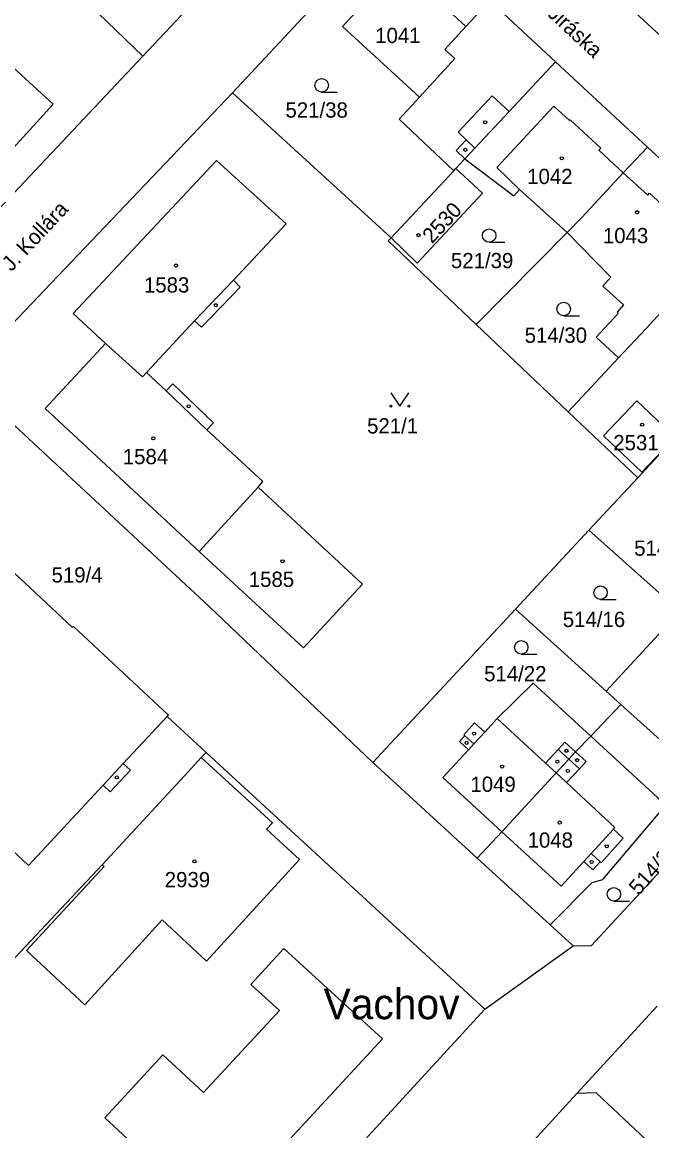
# Model space of a CAD drawing. Extents: x -679220 to -673243, y -1075091 to -1066557.
# Drawn here: x -675907.3 to -675837.1, y -1071866.6 to -1071743.1 of the extents above; entities that cross this region are included whole.
import ezdxf

# ---------------------------------------------------------------- set-up
doc = ezdxf.new("R2010")
doc.units = 0
for name, color, linetype in [('Hranice parcel', 7, 'Continuous'), ('Parcelní čísla', 7, 'Continuous'), ('Pop  PČ popisy', 7, 'Continuous'), ('Vnitřní kresba', 7, 'Continuous'), ('Značky budov', 7, 'Continuous'), ('Značky kultur', 7, 'Continuous')]:
    doc.layers.add(name, color=color, linetype=linetype)

msp = doc.modelspace()

# ---------------------------------------------------------------- linework, layer by layer
at = {"layer": 'Hranice parcel'}
for p, q in [((-675866.48, -1071732.32), (-675883.86, -1071750.99)), ((-675893.86, -1071746.89), (-675880.99, -1071733.17)), ((-675842.49, -1071738.77), (-675830.43, -1071749.89)), ((-675847.84, -1071747.53), (-675855.18, -1071740.72)), ((-675898.85, -1071742.09), (-675893.86, -1071746.89)), ((-675921.25, -1071775.94), (-675893.86, -1071746.89)), ((-675837.59, -1071757.04), (-675847.84, -1071747.53)), ((-675883.86, -1071750.99), (-675914.03, -1071782.61)), ((-675866.19, -1071767.13), (-675883.86, -1071750.99)), ((-675827.58, -1071766.32), (-675837.59, -1071757.04)), ((-675858.95, -1071759.4), (-675857.95, -1071758.34)), ((-675859.18, -1071759.65), (-675866.19, -1071767.13)), ((-675859.18, -1071759.65), (-675858.95, -1071759.4)), ((-675846.56, -1071766.55), (-675856.71, -1071776.78)), ((-675846.56, -1071766.55), (-675841.68, -1071771.5)), ((-675856.71, -1071776.78), (-675846.44, -1071786.53)), ((-675843.31, -1071778.2), (-675840.81, -1071780.5)), ((-675846.44, -1071786.53), (-675840.81, -1071780.5)), ((-675846.44, -1071786.53), (-675838.69, -1071793.89)), ((-675835.95, -1071790.96), (-675838.69, -1071793.89)), ((-675887.58, -1071802.09), (-675881, -1071794.9)), ((-675838.69, -1071793.89), (-675844.12, -1071799.72)), ((-675844.12, -1071799.72), (-675852.3, -1071808.5)), ((-675844.12, -1071799.72), (-675834.93, -1071807.9)), ((-675852.3, -1071808.5), (-675868.22, -1071825.58)), ((-675852.3, -1071808.5), (-675842.22, -1071817.63)), ((-675842.22, -1071817.63), (-675840.56, -1071819.13)), ((-675843.93, -1071822.65), (-675840.56, -1071819.13)), ((-675840.56, -1071819.13), (-675828.84, -1071829.74)), ((-675891.16, -1071820.48), (-675886.79, -1071824.5)), ((-675886.79, -1071824.5), (-675887.37, -1071825.05)), ((-675855.72, -1071853.08), (-675886.79, -1071824.5)), ((-675868.22, -1071825.58), (-675856.58, -1071836.24)), ((-675853.82, -1071833.33), (-675856.58, -1071836.24)), ((-675856.58, -1071836.24), (-675848.43, -1071843.7)), ((-675848.43, -1071843.7), (-675845.89, -1071846.03)), ((-675855.72, -1071853.08), (-675845.89, -1071846.03)), ((-675845.47, -1071862.48), (-675836.53, -1071852.75)), ((-675901.1, -1071902.37), (-675855.72, -1071853.08)), ((-675845.47, -1071862.48), (-675857.63, -1071875.7))]:
    msp.add_line(p, q, dxfattribs=at)
for points in [[(-675855.18, -1071740.72), (-675857.84, -1071743.59), (-675865.26, -1071736.73), (-675871.59, -1071743.6), (-675863.02, -1071751.44), (-675865.29, -1071753.91), (-675859.18, -1071759.65)], [(-675918.94, -1071760.27), (-675914.71, -1071764.13), (-675903.88, -1071752.24), (-675911.09, -1071745.65), (-675921.6, -1071757.18)], [(-675857.95, -1071758.34), (-675856.83, -1071757.13), (-675853.02, -1071753.07), (-675847.84, -1071747.53)], [(-675891.16, -1071820.48), (-675891.02, -1071820.34), (-675901.61, -1071810.45), (-675901.71, -1071810.56), (-675918.81, -1071794.59), (-675918.18, -1071793.92), (-675931.58, -1071781.37), (-675932.2, -1071782.05), (-675949.36, -1071766.12), (-675949.26, -1071766.01), (-675959.87, -1071756.16)], [(-675846.56, -1071766.55), (-675844.9, -1071764.88), (-675840.29, -1071759.88), (-675837.59, -1071757.04)], [(-675893.45, -1071782.14), (-675888.1, -1071776.37), (-675887.31, -1071777.1), (-675883.01, -1071772.64), (-675883.76, -1071771.84), (-675877.9, -1071765.58), (-675885.65, -1071758.5), (-675901.64, -1071775.55), (-675898.01, -1071778.89)], [(-675857.95, -1071758.34), (-675852.5, -1071762.45), (-675851.85, -1071761.73), (-675846.56, -1071766.55)], [(-675866.19, -1071767.13), (-675863.29, -1071769.94), (-675856.01, -1071762.17), (-675858.95, -1071759.4)], [(-675840.81, -1071780.5), (-675837.74, -1071777.22), (-675834.42, -1071773.65), (-675827.58, -1071766.32)], [(-675856.71, -1071776.78), (-675866.51, -1071767.47), (-675866.19, -1071767.13)], [(-675841.68, -1071771.5), (-675842.59, -1071772.51), (-675840.26, -1071774.6), (-675840.99, -1071775.43), (-675840.87, -1071775.55), (-675843.31, -1071778.2)], [(-675898.01, -1071778.89), (-675904.75, -1071786.16), (-675887.58, -1071802.09)], [(-675898.01, -1071778.89), (-675893.92, -1071782.64), (-675893.45, -1071782.14)], [(-675881, -1071794.9), (-675880.5, -1071794.3), (-675886.72, -1071788.53), (-675885.97, -1071787.73), (-675890.53, -1071783.41), (-675891.27, -1071784.2), (-675893.45, -1071782.14)], [(-675868.22, -1071825.58), (-675886.48, -1071808.2), (-675914.03, -1071782.61)], [(-675838.23, -1071793.24), (-675834.52, -1071789.33), (-675838.77, -1071785.29), (-675842.49, -1071789.2), (-675838.23, -1071793.24)], [(-675887.58, -1071802.09), (-675875.94, -1071812.81), (-675869.37, -1071805.71), (-675881, -1071794.9)], [(-675834.93, -1071807.9), (-675835.49, -1071810.37), (-675842.22, -1071817.63)], [(-675843.93, -1071822.65), (-675850.33, -1071816.76), (-675854.35, -1071820.68), (-675855.75, -1071822.21), (-675856.89, -1071821.16), (-675858.06, -1071822.51), (-675857.95, -1071822.61), (-675858.56, -1071823.27), (-675857.56, -1071824.19), (-675860.41, -1071827.28), (-675853.82, -1071833.33)], [(-675917.51, -1071826.9), (-675906.62, -1071837.07), (-675898.28, -1071828.12), (-675897.5, -1071828.86), (-675895.25, -1071826.46), (-675896.04, -1071825.71), (-675891.16, -1071820.48)], [(-675843.93, -1071822.65), (-675845.62, -1071824.41), (-675846.37, -1071825.22), (-675847.79, -1071826.76), (-675853.82, -1071833.33)], [(-675848.43, -1071843.7), (-675843.75, -1071838.95), (-675842.57, -1071838.65), (-675835.54, -1071830.36), (-675843.93, -1071822.65)], [(-675898.39, -1071836.99), (-675898.17, -1071837.19), (-675906.82, -1071846.56), (-675900.34, -1071852.59), (-675891.72, -1071843.14), (-675886.75, -1071847.74), (-675876.4, -1071836.42), (-675880.09, -1071833.04), (-675879.42, -1071832.31), (-675887.37, -1071825.05)], [(-675887.37, -1071825.05), (-675889.26, -1071827.11), (-675898.39, -1071836.99)], [(-675845.89, -1071846.03), (-675843.82, -1071845.98), (-675828.84, -1071829.74)], [(-675898.39, -1071836.99), (-675933.68, -1071874.5), (-675933.54, -1071880.78), (-675913, -1071900.25)], [(-675879.3, -1071869.55), (-675867.15, -1071856.4), (-675878.15, -1071846.32), (-675881.81, -1071850.32), (-675878.64, -1071853.22), (-675887.1, -1071862.37), (-675891.64, -1071858.18), (-675898.1, -1071865.18), (-675893.57, -1071869.37), (-675900, -1071876.33), (-675900.67, -1071875.72), (-675902.04, -1071877.21), (-675902.65, -1071876.64), (-675903.4, -1071877.45), (-675905.25, -1071875.74), (-675908.95, -1071879.75), (-675898.03, -1071889.82), (-675885.83, -1071876.61), (-675885.72, -1071876.72), (-675879.19, -1071869.65), (-675879.3, -1071869.55)], [(-675832.83, -1071872.25), (-675843.33, -1071862.41), (-675845.47, -1071862.48)]]:
    msp.add_lwpolyline(points, dxfattribs=at)
at = {"layer": 'Vnitřní kresba'}
for p, q in [((-675857.84, -1071743.59), (-675860.18, -1071746.13)), ((-675860.18, -1071746.13), (-675859.09, -1071747.14)), ((-675859.09, -1071747.14), (-675863.02, -1071751.44)), ((-675858.7, -1071755.37), (-675854.9, -1071751.32)), ((-675854.9, -1071751.32), (-675853.02, -1071753.07)), ((-675854.38, -1071759.31), (-675848.04, -1071752.46)), ((-675848.04, -1071752.46), (-675846.3, -1071754.07)), ((-675846.3, -1071754.07), (-675846.22, -1071753.99)), ((-675846.22, -1071753.99), (-675842.81, -1071757.15)), ((-675857.8, -1071756.22), (-675858.7, -1071755.37)), ((-675858.93, -1071757.42), (-675857.8, -1071756.22)), ((-675857.8, -1071756.22), (-675856.83, -1071757.13)), ((-675857.95, -1071758.34), (-675858.93, -1071757.42)), ((-675842.81, -1071757.15), (-675843.01, -1071757.37)), ((-675843.01, -1071757.37), (-675840.29, -1071759.88)), ((-675851.85, -1071761.73), (-675854.38, -1071759.31)), ((-675840.29, -1071759.88), (-675837.57, -1071762.39)), ((-675837.57, -1071762.39), (-675837.37, -1071762.17)), ((-675837.37, -1071762.17), (-675833.95, -1071765.32)), ((-675888.1, -1071776.37), (-675883.76, -1071771.84)), ((-675891.27, -1071784.2), (-675886.72, -1071788.53)), ((-675848.97, -1071825.68), (-675854.35, -1071820.68)), ((-675857.95, -1071822.61), (-675856.96, -1071823.52)), ((-675856.96, -1071823.52), (-675855.75, -1071822.21)), ((-675847.54, -1071824.13), (-675846.8, -1071823.32)), ((-675846.8, -1071823.32), (-675845.62, -1071824.41)), ((-675856.96, -1071823.52), (-675857.56, -1071824.19)), ((-675848.97, -1071825.68), (-675847.54, -1071824.13)), ((-675847.54, -1071824.13), (-675846.37, -1071825.22)), ((-675845.62, -1071824.41), (-675844.44, -1071825.49)), ((-675898.28, -1071828.12), (-675896.04, -1071825.71)), ((-675847.79, -1071826.76), (-675848.97, -1071825.68)), ((-675846.37, -1071825.22), (-675845.19, -1071826.3)), ((-675844.44, -1071825.49), (-675845.19, -1071826.3)), ((-675846.61, -1071827.84), (-675847.79, -1071826.76)), ((-675845.19, -1071826.3), (-675846.61, -1071827.84)), ((-675841.23, -1071832.85), (-675846.61, -1071827.84)), ((-675843.89, -1071835.73), (-675841.4, -1071833.03)), ((-675841.4, -1071833.03), (-675841.23, -1071832.85)), ((-675841.4, -1071833.03), (-675840.29, -1071834.04)), ((-675853.82, -1071833.33), (-675847.23, -1071839.38)), ((-675840.29, -1071834.04), (-675842.77, -1071836.76)), ((-675847.23, -1071839.38), (-675844.71, -1071836.62)), ((-675844.71, -1071836.62), (-675843.89, -1071835.73)), ((-675843.69, -1071837.55), (-675844.71, -1071836.62)), ((-675843.89, -1071835.73), (-675842.88, -1071836.66)), ((-675842.88, -1071836.66), (-675843.69, -1071837.55)), ((-675842.77, -1071836.76), (-675842.88, -1071836.66))]:
    msp.add_line(p, q, dxfattribs=at)
at = {"layer": 'Značky budov'}
for centre in [(-675855.7, -1071754.26), (-675857.9, -1071757.33), (-675847.15, -1071758.27), (-675838.74, -1071764.28), (-675863.13, -1071766.84), (-675890.17, -1071770.21), (-675885.73, -1071774.63), (-675888.76, -1071785.91), (-675838.19, -1071787.96), (-675892.7, -1071789.47), (-675878.29, -1071803.17), (-675857.75, -1071823.41), (-675856.92, -1071822.38), (-675846.63, -1071824.3), (-675847.64, -1071825.51), (-675845.44, -1071825.34), (-675853.8, -1071826.06), (-675846.47, -1071826.54), (-675896.76, -1071827.26), (-675847.39, -1071832.29), (-675842.13, -1071834.93), (-675888.1, -1071836.61), (-675843.83, -1071836.68)]:
    msp.add_circle(centre, 0.175, dxfattribs=at)
at = {"layer": 'Značky kultur'}
for p, q in [((-675873.93, -1071750.89), (-675872.18, -1071750.89)), ((-675855.25, -1071767.63), (-675853.5, -1071767.63)), ((-675846.94, -1071775.81), (-675845.19, -1071775.81)), ((-675842.83, -1071807.42), (-675841.08, -1071807.42)), ((-675851.67, -1071813.51), (-675849.92, -1071813.51)), ((-675841.34, -1071841.03), (-675839.59, -1071841.03))]:
    msp.add_line(p, q, dxfattribs=at)
msp.add_lwpolyline([(-675866.22, -1071784.39), (-675865.22, -1071785.89), (-675864.22, -1071784.39)], dxfattribs=at)
for centre, radius in [((-675873.93, -1071750.14), 0.75), ((-675855.25, -1071766.88), 0.75), ((-675846.94, -1071775.06), 0.75), ((-675866.22, -1071785.89), 0.1), ((-675864.22, -1071785.89), 0.1), ((-675842.83, -1071806.67), 0.75), ((-675851.67, -1071812.76), 0.75), ((-675841.34, -1071840.28), 0.75)]:
    msp.add_circle(centre, radius, dxfattribs=at)

# ---------------------------------------------------------------- texts
at = {"layer": 'Parcelní čísla'}
for s, p in [('1041', (-675867.96, -1071745.43)), ('521/38', (-675877.96, -1071753.74)), ('1042', (-675851.01, -1071761.14)), ('1043', (-675842.57, -1071767.73)), ('521/39', (-675859.51, -1071770.52)), ('1583', (-675893.74, -1071773.23)), ('514/30', (-675851.29, -1071778.83)), ('521/1', (-675868.86, -1071788.93)), ('2531', (-675841.41, -1071790.8)), ('1584', (-675896.1, -1071792.36)), ('514/14', (-675839.08, -1071802.56)), ('519/4', (-675904.04, -1071805.54)), ('1585', (-675882.05, -1071806.03)), ('514/16', (-675847.04, -1071810.5)), ('514/22', (-675855.81, -1071816.55)), ('1049', (-675857.34, -1071828.87)), ('1048', (-675850.96, -1071835.09)), ('2939', (-675891.42, -1071839.5))]:
    msp.add_text(s, height=1.7, dxfattribs=at).set_placement(p)
for s, rotation, p in [('2530', 47, (-675861.62, -1071767.86)), ('514/23', 48, (-675838.58, -1071840.49))]:
    msp.add_text(s, height=1.7, rotation=rotation, dxfattribs=at).set_placement(p)
at = {"layer": 'Pop  PČ popisy'}
for s, rotation, p in [('Al. Jiráska', 317, (-675851.26, -1071740.05)), ('J. Kollára', 47, (-675908.52, -1071770.97))]:
    msp.add_text(s, height=1.7, rotation=rotation, dxfattribs=at).set_placement(p)
msp.add_text('Vachov', height=3.4, dxfattribs=at).set_placement((-675873.72, -1071854.2))

doc.saveas('drawing.dxf')
